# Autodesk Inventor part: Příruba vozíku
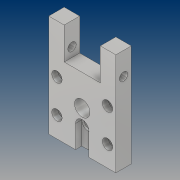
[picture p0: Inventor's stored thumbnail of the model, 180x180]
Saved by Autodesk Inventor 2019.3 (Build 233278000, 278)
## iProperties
Created: 2019-01
Part Number: Příruba vozíku
Material: Hliník 6061-AHC
Document SubType Name: Modeling
Designer: B-hon
Density: 2.7 g/cm^3
Appearance: Hliník – tmavý
Author: B-hon
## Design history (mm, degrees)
sketch "Náčrt1"
  geometry: L1 (-24.5, 16)-(24.5, 16); L2 (24.5, 16)-(24.5, -16); L3 (24.5, -16)-(-24.5, -16); L4 (-24.5, -16)-(-24.5, 16); L5 (-24.5, 16)-(24.5, -16); L6 (24.5, 16)-(-24.5, -16); L7 (32.5, -24)-(-32.5, -24); L8 (-32.5, -24)-(-32.5, 56); L9 (32.5, 56)-(32.5, -24); L10 (-32.5, 56)-(32.5, 56); 1 further point
  constraints: 20 end point, 3 horizontal, 3 parallel, 2 midpoint, 2 perpendicular
  dimensions: "d0" = 49 distance of L2.end L3.end; "d1" = 32 distance of L1.end L2.end; "d4" = 80 distance between parallel lines of L7 L10; "d21" = 8 distance between parallel lines of L9 L2; "d22" = 8 distance between parallel lines of L4 L8; "d23" = 8 distance between parallel lines of L7 L3
extrude "Vysunutí1" new body sketch "Náčrt1" distance "d5" = 12; taper "d6" = 0 deg
sketch "Náčrt2"
  geometry: L1 (0, 80)-(0, 0) reference; L2 (0, 0)-(-12, 0) reference; 2 further points
  dimensions: "d7" = 4.5 distance from line of L1 point (-4.5, 65); "d8" = 65 distance from line of L2 point (-4.5, 65)
hole "Díra1" sketch "Náčrt2" at (-4.5, 65) diameter "d9" = 8; stored, may be unused: countersink angle "d13" = 90 deg, drill point angle "d15" = 118 deg; dims "d10" = 6, "d11" = 4, "d12" = 2, "d14" = 8
sketch "Náčrt3"
  geometry: L1 (32.5, 56)-(-32.5, 56) reference; L2 (-17.5, 56)-(17.5, 56); L3 (17.5, 56)-(17.5, 32); L4 (17.5, 32)-(-17.5, 32); L5 (-17.5, 32)-(-17.5, 56); L6 (-32.5, -24)-(32.5, -24) reference; 1 further point
  constraints: 8 end point, 2 parallel, 1 horizontal, 1 perpendicular, 1 point on line
  dimensions: "d16" = 56 distance between parallel lines of L4 L6; "d17" = 35 distance of L3.end L4.end; "d18" = 15 distance from line of L1.end L5
extrude "Vysunutí2" cut sketch "Náčrt3" distance "d19" = 12; taper "d20" = 0 deg
sketch "Náčrt5"
  geometry: L1 (-24.5, 16)-(24.5, 16); L2 (24.5, 16)-(24.5, -16); L3 (24.5, -16)-(-24.5, -16); L4 (-24.5, -16)-(-24.5, 16); L5 (-24.5, 16)-(24.5, -16); L6 (24.5, 16)-(-24.5, -16); 5 further points
  constraints: 12 end point, 4 coincident, 2 midpoint, 2 parallel, 1 horizontal, 1 perpendicular
  dimensions: "d24" = 49 distance of L2.end L3.end; "d25" = 32 distance of L1.end L2.end
hole "Díra2" sketch "Náčrt5" at (-24.5, 16), (24.5, 16), (24.5, -16), (-24.5, -16) diameter "d26" = 5.3; stored, may be unused: countersink angle "d30" = 90 deg, drill point angle "d32" = 118 deg; dims "d27" = 6, "d28" = 10, "d29" = 5.7, "d31" = 8
node "Upravit přímo1"
sketch "Náčrt6"
  geometry: L1 (-32.5, -24)-(32.5, -24) reference; C1 r 6.5 at (0, -14); 1 further point
  constraints: 1 centre point
  dimensions: "d36" = 13 diameter of C1; "d37" = 10 distance from line of L1 C1.centre
extrude "Vysunutí3" cut sketch "Náčrt6" distance "d38" = 8; taper "d39" = 0 deg
sketch "Náčrt7"
  geometry: L1 (6.5, -48.468)-(-6.5, -48.468); L2 (-6.5, -48.468)-(-6.5, -14); L3 (-6.5, -14)-(6.5, -14); L4 (6.5, -14)-(6.5, -48.468); L5 (6.5, -48.468)-(-6.5, -14); L6 (-6.5, -48.468)-(6.5, -14); 3 further points
  constraints: 12 end point, 2 midpoint, 2 parallel, 1 horizontal, 1 horizontal alignment, 1 perpendicular, 1 other
  dimensions: "d40" = 13 distance of L2.end L3.end
extrude "Vysunutí4" cut sketch "Náčrt7" distance "d41" = 6; taper "d42" = 0 deg
node "Upravit přímo2"
sketch "Náčrt8"
  geometry: L1 (-32.5, -24)-(-6.5, -24) reference; L2 (-32.5, 63)-(-32.5, -24) reference; 2 further points
  dimensions: "d46" = 26 distance from line of L1 point (0, 2); "d47" = 32.5 distance from line of L2 point (0, 2)
hole "Díra3" sketch "Náčrt8" at (0, 2) diameter "d48" = 15; stored, may be unused: countersink angle "d52" = 90 deg, drill point angle "d54" = 118 deg; dims "d49" = 6, "d50" = 4, "d51" = 2, "d53" = 13
node "Upravit přímo4"
sketch "Náčrt12"
  geometry: L1 (0, 0)-(0, 15) reference; L2 (65, 0)-(0, 0) reference; 3 further points
  constraints: 1 horizontal alignment
  dimensions: "d91" = 52 distance of point (58.5, 7.5) point (6.5, 7.5); "d92" = 6.5 distance from line of L1 point (6.5, 7.5); "d93" = 7.5 distance from line of L2 point (6.5, 7.5)
hole "Díra7" sketch "Náčrt12" at (6.5, 7.5), (58.5, 7.5) diameter "d94" = 4.917; stored, may be unused: countersink angle "d98" = 90 deg, drill point angle "d100" = 0 deg; dims "d95" = 13, "d96" = 6, "d97" = 2, "d99" = 14.7
node "Těleso1"
feature "Posunout1" dims "d35" = 7
feature "Posunout2" dims "d45" = 3
feature "Posunout4" dims "d90" = 12
other parameters: "d33" = 0, "d34" = 0, "d43" = 0, "d44" = 0, "d88" = 0, "d89" = 0
